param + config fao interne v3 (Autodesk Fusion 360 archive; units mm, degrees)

design "param + config fao interne"
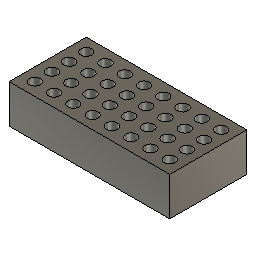
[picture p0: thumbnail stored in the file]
part number: Configuration 3
parameter "longueur" = 250
parameter "largeur" = 120
parameter "hauteurext" = 60
parameter "dlamage" = 17
sketch "Esquisse1" plane through (0, 0, 0) normal (0, 0, 1) x axis (1, 0, 0)
  line L1 (-125, -60) -> (125, -60)
  line L2 (-125, 60) -> (-125, -60)
  line L3 (125, 60) -> (-125, 60)
  line L4 (125, -60) -> (125, 60)
  line L5 (-125, 60) -> (125, -60)
  line L6 (125, 60) -> (-125, -60)
  point P6 (0, 0)
  point P1 (0, 0)
  point P4 (-125, 60)
  point P5 (125, 60)
  point P3 (-125, -60)
  horizontal L1
  perpendicular L1 L2
  parallel L1 L3
  parallel L2 L4
  coincident L5 P6
  coincident L6 P6
  coincident P1 P6
  dimension "d3" distance P4 P5 = 250 (= "longueur")
  dimension "d4" distance P3 P4 = 120 (= "largeur")
extrude "Extrusion" new body sketch "Esquisse1" profile of L1 L2 L3 L4 along normal blind 60 (= "hauteurext") named "hauteur"
sketch "Esquisse2" plane through (0, 0, 60) normal (0, 0, 1) x axis (-1, 0, 0)
  line L1 (125, -60) -> (-125, -60)
  line L2 (125, 60) -> (125, -60)
  point P2 (105, -40)
  dimension "d8" distance P2 L1 = 20
  dimension "d9" distance P2 L2 = 20
  dimension "d12" R-Pattern1-uDistance = -30 (= "-( longueur - 40 mm ) / ( nb_de_trous - 1 )")
  dimension "d13" R-Pattern1-vDistance = 26.6667 (= "( largeur - 40 mm ) / ( floor(nb_de_trous) / 2 - 1 )")
hole "Perçage1" HoleDiameter 8.5 (= "dlamage / 2") CBDepth 12 (= "hauteurext / 5") CBDiameter 17 (= "dlamage") named "dlam"
hole "Perçage2" HoleDiameter 8.5 (= "dlamage / 2") CBDepth 12 (= "hauteurext / 5") CBDiameter 17 (= "dlamage")
hole "Perçage3" HoleDiameter 8.5 (= "dlamage / 2") CBDepth 12 (= "hauteurext / 5") CBDiameter 17 (= "dlamage")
